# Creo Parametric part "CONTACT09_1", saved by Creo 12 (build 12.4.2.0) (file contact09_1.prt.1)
Units: Custom; MM, KILOGRAM, SECS

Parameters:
  PTC_WM_ITERATION = "0"
  PTC_WM_VERSION = "-.0"
  PTC_WM_LIFECYCLE_STATE = "In Work"
  PTC_WM_LIFECYCLE = "MO_CADDocument"
  PTC_WM_CREATED_BY = "Maximilian Roepper (Z0017RMS: MO)"
  PTC_WM_CREATED_ON = "18-Sep-26 11:36:42 AM"
  PTC_WM_MODIFIED_BY = "Maximilian Roepper (Z0017RMS: MO)"
  PTC_WM_MODIFIED_ON = "18-Sep-26 11:36:46 AM"
  PDMLINKNUMBER = "PDM000071454846"
  PTC_WM_NAME = "contact09_1.prt"
  PTC_WM_NUMBER = "PDM000071454846"

Other parameters: WEIGHT, WEIGHT_FACTOR, WEIGHT_ADD, _MASS_TEMP, _DIFF_TEMP, MC_ERRORS, SUPPLIER

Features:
  1. coordinate system
  2. datum plane "PRT_YZ"
  3. datum plane "PRT_XY"
  4. datum plane "PRT_XZ"
  5. coordinate system
  6. datum axis
  7. datum axis
  8. datum axis
  9. coordinate system
  10. imported feature

Other named items: PRT, SIEMENS_MO, DRW_VIEW_ORG, PRT_X, PRT_Y, PRT_Z, CS0, ROUGH_GROB

Layers: 00_STD_CSYS-KSYS, 01_STD_PLANES-EBENEN, 02_STD_AXES-ACHSEN, 03_STD_CSYS-KSYS, 24_IMPORT_FEAT-IMPORT_KE

Surfaces: 12 plane, 6 cylinder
